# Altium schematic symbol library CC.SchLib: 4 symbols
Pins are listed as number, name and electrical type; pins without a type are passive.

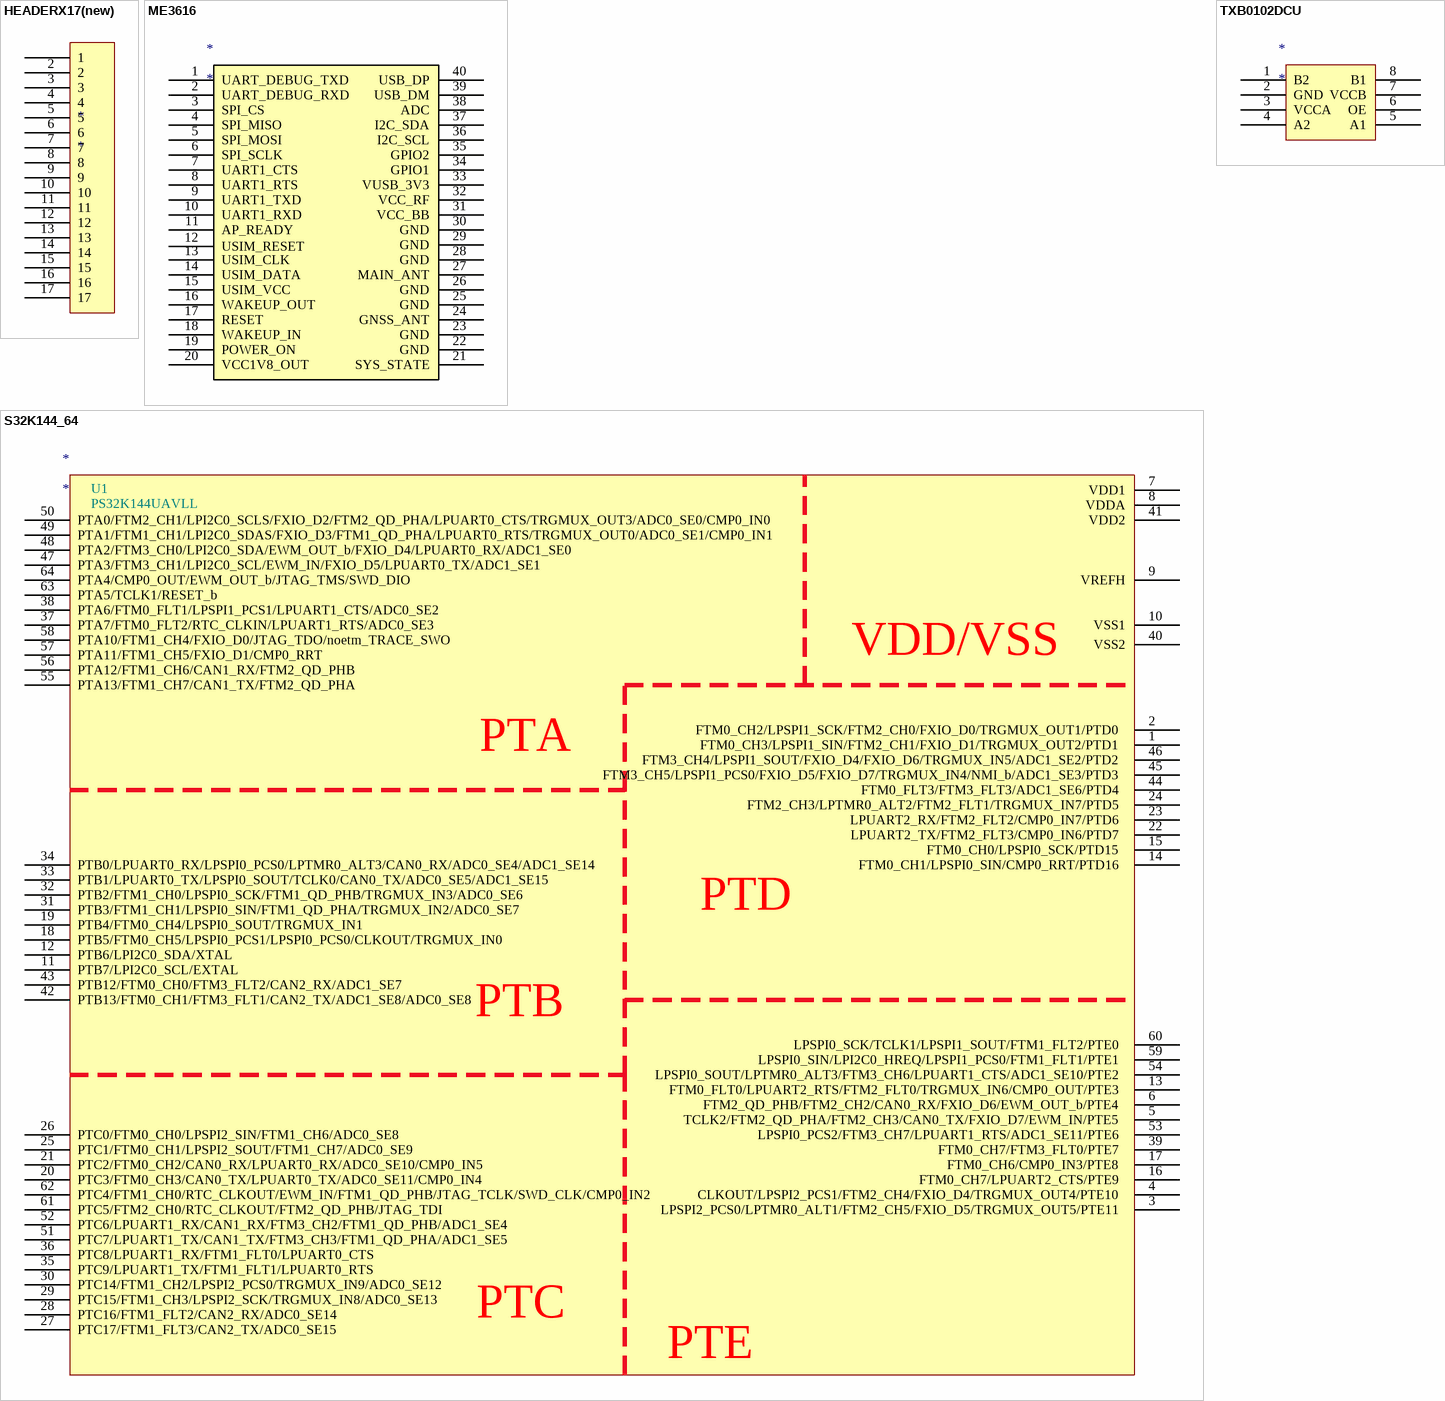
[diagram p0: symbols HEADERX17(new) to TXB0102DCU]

## HEADERX17(new)
designator *
footprint HEADERX17(new)
pins: 1, 2, 3, 4, 5, 6, 7, 8, 9, 10, 11, 12, 13, 14, 15, 16, 17

## ME3616
designator *
footprint ME3616
pins: 1 UART_DEBUG_TXD, 2 UART_DEBUG_RXD, 3 SPI_CS, 4 SPI_MISO, 5 SPI_MOSI, 6 SPI_SCLK, 7 UART1_CTS, 8 UART1_RTS, 9 UART1_TXD, 10 UART1_RXD, 11 AP_READY, 12 USIM_RESET, 13 USIM_CLK, 14 USIM_DATA, 15 USIM_VCC, 16 WAKEUP_OUT, 17 RESET, 18 WAKEUP_IN, 19 POWER_ON, 20 VCC1V8_OUT, 21 SYS_STATE, 22 GND, 23 GND, 24 GNSS_ANT, 25 GND, 26 GND, 27 MAIN_ANT, 28 GND, 29 GND, 30 GND, 31 VCC_BB, 32 VCC_RF, 33 VUSB_3V3, 34 GPIO1, 35 GPIO2, 36 I2C_SCL, 37 I2C_SDA, 38 ADC, 39 USB_DM, 40 USB_DP

## S32K144_64
designator *
footprint LQFP64
pins: 1 FTM0_CH3/LPSPI1_SIN/FTM2_CH1/FXIO_D1/TRGMUX_OUT2/PTD1  , 2 FTM0_CH2/LPSPI1_SCK/FTM2_CH0/FXIO_D0/TRGMUX_OUT1/PTD0  , 3 LPSPI2_PCS0/LPTMR0_ALT1/FTM2_CH5/FXIO_D5/TRGMUX_OUT5/PTE11  , 4 CLKOUT/LPSPI2_PCS1/FTM2_CH4/FXIO_D4/TRGMUX_OUT4/PTE10  , 5 TCLK2/FTM2_QD_PHA/FTM2_CH3/CAN0_TX/FXIO_D7/EWM_IN/PTE5  , 6 FTM2_QD_PHB/FTM2_CH2/CAN0_RX/FXIO_D6/EWM_OUT_b/PTE4  , 7 VDD1, 8 VDDA, 9 VREFH, 10 VSS1, 11 PTB7/LPI2C0_SCL/EXTAL  , 12 PTB6/LPI2C0_SDA/XTAL  , 13 FTM0_FLT0/LPUART2_RTS/FTM2_FLT0/TRGMUX_IN6/CMP0_OUT/PTE3  , 14 FTM0_CH1/LPSPI0_SIN/CMP0_RRT/PTD16  , 15 FTM0_CH0/LPSPI0_SCK/PTD15  , 16 FTM0_CH7/LPUART2_CTS/PTE9  , 17 FTM0_CH6/CMP0_IN3/PTE8  , 18 PTB5/FTM0_CH5/LPSPI0_PCS1/LPSPI0_PCS0/CLKOUT/TRGMUX_IN0  , 19 PTB4/FTM0_CH4/LPSPI0_SOUT/TRGMUX_IN1  , 20 PTC3/FTM0_CH3/CAN0_TX/LPUART0_TX/ADC0_SE11/CMP0_IN4  , 21 PTC2/FTM0_CH2/CAN0_RX/LPUART0_RX/ADC0_SE10/CMP0_IN5  , 22 LPUART2_TX/FTM2_FLT3/CMP0_IN6/PTD7  , 23 LPUART2_RX/FTM2_FLT2/CMP0_IN7/PTD6  , 24 FTM2_CH3/LPTMR0_ALT2/FTM2_FLT1/TRGMUX_IN7/PTD5  , 25 PTC1/FTM0_CH1/LPSPI2_SOUT/FTM1_CH7/ADC0_SE9  , 26 PTC0/FTM0_CH0/LPSPI2_SIN/FTM1_CH6/ADC0_SE8  , 27 PTC17/FTM1_FLT3/CAN2_TX/ADC0_SE15  , 28 PTC16/FTM1_FLT2/CAN2_RX/ADC0_SE14  , 29 PTC15/FTM1_CH3/LPSPI2_SCK/TRGMUX_IN8/ADC0_SE13  , 30 PTC14/FTM1_CH2/LPSPI2_PCS0/TRGMUX_IN9/ADC0_SE12  , 31 PTB3/FTM1_CH1/LPSPI0_SIN/FTM1_QD_PHA/TRGMUX_IN2/ADC0_SE7  , 32 PTB2/FTM1_CH0/LPSPI0_SCK/FTM1_QD_PHB/TRGMUX_IN3/ADC0_SE6  , 33 PTB1/LPUART0_TX/LPSPI0_SOUT/TCLK0/CAN0_TX/ADC0_SE5/ADC1_SE15  , 34 PTB0/LPUART0_RX/LPSPI0_PCS0/LPTMR0_ALT3/CAN0_RX/ADC0_SE4/ADC1_SE14  , 35 PTC9/LPUART1_TX/FTM1_FLT1/LPUART0_RTS  , 36 PTC8/LPUART1_RX/FTM1_FLT0/LPUART0_CTS  , 37 PTA7/FTM0_FLT2/RTC_CLKIN/LPUART1_RTS/ADC0_SE3  , 38 PTA6/FTM0_FLT1/LPSPI1_PCS1/LPUART1_CTS/ADC0_SE2  , 39 FTM0_CH7/FTM3_FLT0/PTE7  , 40 VSS2, 41 VDD2, 42 PTB13/FTM0_CH1/FTM3_FLT1/CAN2_TX/ADC1_SE8/ADC0_SE8  , 43 PTB12/FTM0_CH0/FTM3_FLT2/CAN2_RX/ADC1_SE7  , 44 FTM0_FLT3/FTM3_FLT3/ADC1_SE6/PTD4  , 45 FTM3_CH5/LPSPI1_PCS0/FXIO_D5/FXIO_D7/TRGMUX_IN4/NMI_b/ADC1_SE3/PTD3  , 46 FTM3_CH4/LPSPI1_SOUT/FXIO_D4/FXIO_D6/TRGMUX_IN5/ADC1_SE2/PTD2  , 47 PTA3/FTM3_CH1/LPI2C0_SCL/EWM_IN/FXIO_D5/LPUART0_TX/ADC1_SE1  , 48 PTA2/FTM3_CH0/LPI2C0_SDA/EWM_OUT_b/FXIO_D4/LPUART0_RX/ADC1_SE0  , 49 PTA1/FTM1_CH1/LPI2C0_SDAS/FXIO_D3/FTM1_QD_PHA/LPUART0_RTS/TRGMUX_OUT0/ADC0_SE1/CMP0_IN1, 50 PTA0/FTM2_CH1/LPI2C0_SCLS/FXIO_D2/FTM2_QD_PHA/LPUART0_CTS/TRGMUX_OUT3/ADC0_SE0/CMP0_IN0, 51 PTC7/LPUART1_TX/CAN1_TX/FTM3_CH3/FTM1_QD_PHA/ADC1_SE5  , 52 PTC6/LPUART1_RX/CAN1_RX/FTM3_CH2/FTM1_QD_PHB/ADC1_SE4  , 53 LPSPI0_PCS2/FTM3_CH7/LPUART1_RTS/ADC1_SE11/PTE6  , 54 LPSPI0_SOUT/LPTMR0_ALT3/FTM3_CH6/LPUART1_CTS/ADC1_SE10/PTE2  , 55 PTA13/FTM1_CH7/CAN1_TX/FTM2_QD_PHA  , 56 PTA12/FTM1_CH6/CAN1_RX/FTM2_QD_PHB  , 57 PTA11/FTM1_CH5/FXIO_D1/CMP0_RRT  , 58 PTA10/FTM1_CH4/FXIO_D0/JTAG_TDO/noetm_TRACE_SWO  , 59 LPSPI0_SIN/LPI2C0_HREQ/LPSPI1_PCS0/FTM1_FLT1/PTE1  , 60 LPSPI0_SCK/TCLK1/LPSPI1_SOUT/FTM1_FLT2/PTE0  , 61 PTC5/FTM2_CH0/RTC_CLKOUT/FTM2_QD_PHB/JTAG_TDI  , 62 PTC4/FTM1_CH0/RTC_CLKOUT/EWM_IN/FTM1_QD_PHB/JTAG_TCLK/SWD_CLK/CMP0_IN2  , 63 PTA5/TCLK1/RESET_b  , 64 PTA4/CMP0_OUT/EWM_OUT_b/JTAG_TMS/SWD_DIO  

## TXB0102DCU
designator *
pins: 1 B2, 2 GND, 3 VCCA, 4 A2, 5 A1, 6 OE, 7 VCCB, 8 B1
